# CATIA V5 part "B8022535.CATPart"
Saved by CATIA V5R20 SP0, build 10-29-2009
Part number: B8022535
Revision: 7
Definition: design
Nomenclature: B8022535
Source: made
Description: NOT SPECIFIED
Bounding box of the stored display mesh (mm): x -22.5 to 22.5, y -22.5 to 22.5, z -10 to 35
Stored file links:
  C:\Users\Utente\Desktop\3D files B802\B8022535.CATPart
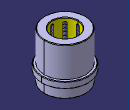
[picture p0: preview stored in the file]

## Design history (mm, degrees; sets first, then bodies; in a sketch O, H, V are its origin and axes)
Body1 "MANIFOLD_SOLID_BREP #38" (main body)
  Solid1: solid without history
Body2 "MANIFOLD_SOLID_BREP #76"
  Solid2: solid without history
Body3 "MANIFOLD_SOLID_BREP #114"
  Solid3: solid without history
Body4 "MANIFOLD_SOLID_BREP #152"
  Solid4: solid without history
Body5 "MANIFOLD_SOLID_BREP #190"
  Solid5: solid without history
Body6 "MANIFOLD_SOLID_BREP #228"
  Solid6: solid without history
Body7 "MANIFOLD_SOLID_BREP #266"
  Solid7: solid without history
Body8 "MANIFOLD_SOLID_BREP #304"
  Solid8: solid without history
Body9 "MANIFOLD_SOLID_BREP #2364"
  Solid9: solid without history
Body10 "MANIFOLD_SOLID_BREP #2402"
  Solid10: solid without history
Body11 "MANIFOLD_SOLID_BREP #2440"
  Solid11: solid without history
Body12 "MANIFOLD_SOLID_BREP #2478"
  Solid12: solid without history
Body13 "MANIFOLD_SOLID_BREP #2516"
  Solid13: solid without history
Body14 "MANIFOLD_SOLID_BREP #2554"
  Solid14: solid without history
Body15 "MANIFOLD_SOLID_BREP #2592"
  Solid15: solid without history
Body16 "MANIFOLD_SOLID_BREP #2630"
  Solid16: solid without history
Body17 "MANIFOLD_SOLID_BREP #2668"
  Solid17: solid without history
Body18 "MANIFOLD_SOLID_BREP #2706"
  Solid18: solid without history
Body19 "MANIFOLD_SOLID_BREP #2744"
  Solid19: solid without history
Body20 "MANIFOLD_SOLID_BREP #2782"
  Solid20: solid without history
Body21 "MANIFOLD_SOLID_BREP #2820"
  Solid21: solid without history
Body22 "MANIFOLD_SOLID_BREP #2858"
  Solid22: solid without history
Body23 "MANIFOLD_SOLID_BREP #2896"
  Solid23: solid without history
Body24 "MANIFOLD_SOLID_BREP #2934"
  Solid24: solid without history
Body25 "MANIFOLD_SOLID_BREP #2972"
  Solid25: solid without history
Body26 "MANIFOLD_SOLID_BREP #3010"
  Solid26: solid without history
Body27 "MANIFOLD_SOLID_BREP #3048"
  Solid27: solid without history
Body28 "MANIFOLD_SOLID_BREP #3086"
  Solid28: solid without history
Body29 "MANIFOLD_SOLID_BREP #3124"
  Solid29: solid without history
Body30 "MANIFOLD_SOLID_BREP #3162"
  Solid30: solid without history
Body31 "MANIFOLD_SOLID_BREP #3200"
  Solid31: solid without history
Body32 "MANIFOLD_SOLID_BREP #3238"
  Solid32: solid without history
Body33 "MANIFOLD_SOLID_BREP #3276"
  Solid33: solid without history
Body34 "MANIFOLD_SOLID_BREP #3314"
  Solid34: solid without history
Body35 "MANIFOLD_SOLID_BREP #3352"
  Solid35: solid without history
Body36 "MANIFOLD_SOLID_BREP #3390"
  Solid36: solid without history
Body37 "MANIFOLD_SOLID_BREP #3428"
  Solid37: solid without history
Body38 "MANIFOLD_SOLID_BREP #3466"
  Solid38: solid without history
Body39 "MANIFOLD_SOLID_BREP #3504"
  Solid39: solid without history
Body40 "MANIFOLD_SOLID_BREP #3542"
  Solid40: solid without history
Body41 "MANIFOLD_SOLID_BREP #3580"
  Solid41: solid without history
Body42 "MANIFOLD_SOLID_BREP #3618"
  Solid42: solid without history
Body43 "MANIFOLD_SOLID_BREP #3656"
  Solid43: solid without history
Body44 "MANIFOLD_SOLID_BREP #3694"
  Solid44: solid without history
Body45 "MANIFOLD_SOLID_BREP #3732"
  Solid45: solid without history
Body46 "MANIFOLD_SOLID_BREP #3770"
  Solid46: solid without history
Body47 "MANIFOLD_SOLID_BREP #3808"
  Solid47: solid without history
Body48 "MANIFOLD_SOLID_BREP #3846"
  Solid48: solid without history
Body49 "MANIFOLD_SOLID_BREP #3884"
  Solid49: solid without history
Body50 "MANIFOLD_SOLID_BREP #3922"
  Solid50: solid without history
Body51 "MANIFOLD_SOLID_BREP #3960"
  Solid51: solid without history
Body52 "MANIFOLD_SOLID_BREP #3998"
  Solid52: solid without history
Body53 "MANIFOLD_SOLID_BREP #4036"
  Solid53: solid without history
Body54 "MANIFOLD_SOLID_BREP #4074"
  Solid54: solid without history
Body55 "MANIFOLD_SOLID_BREP #4112"
  Solid55: solid without history
Body56 "MANIFOLD_SOLID_BREP #4150"
  Solid56: solid without history
Body57 "MANIFOLD_SOLID_BREP #4188"
  Solid57: solid without history
Body58 "MANIFOLD_SOLID_BREP #4226"
  Solid58: solid without history
Body59 "MANIFOLD_SOLID_BREP #4264"
  Solid59: solid without history
Body60 "MANIFOLD_SOLID_BREP #4302"
  Solid60: solid without history
Body61 "MANIFOLD_SOLID_BREP #4340"
  Solid61: solid without history
Body62 "MANIFOLD_SOLID_BREP #4378"
  Solid62: solid without history
Body63 "MANIFOLD_SOLID_BREP #4416"
  Solid63: solid without history
Body64 "MANIFOLD_SOLID_BREP #4454"
  Solid64: solid without history
Body65 "MANIFOLD_SOLID_BREP #4492"
  Solid65: solid without history
Body66 "MANIFOLD_SOLID_BREP #4530"
  Solid66: solid without history
Body67 "MANIFOLD_SOLID_BREP #4568"
  Solid67: solid without history
Body68 "MANIFOLD_SOLID_BREP #4606"
  Solid68: solid without history
Body69 "MANIFOLD_SOLID_BREP #4644"
  Solid69: solid without history
Body70 "MANIFOLD_SOLID_BREP #4682"
  Solid70: solid without history
Body71 "MANIFOLD_SOLID_BREP #4720"
  Solid71: solid without history
Body72 "MANIFOLD_SOLID_BREP #4758"
  Solid72: solid without history
Body73 "MANIFOLD_SOLID_BREP #4796"
  Solid73: solid without history
Body74 "MANIFOLD_SOLID_BREP #4834"
  Solid74: solid without history
Body75 "MANIFOLD_SOLID_BREP #4872"
  Solid75: solid without history
Body76 "MANIFOLD_SOLID_BREP #4910"
  Solid76: solid without history
Body77 "MANIFOLD_SOLID_BREP #4948"
  Solid77: solid without history
Body78 "MANIFOLD_SOLID_BREP #4986"
  Solid78: solid without history
Body79 "MANIFOLD_SOLID_BREP #5024"
  Solid79: solid without history
Body80 "MANIFOLD_SOLID_BREP #5062"
  Solid80: solid without history
Body81 "MANIFOLD_SOLID_BREP #5100"
  Solid81: solid without history
Body82 "MANIFOLD_SOLID_BREP #5138"
  Solid82: solid without history
Body83 "MANIFOLD_SOLID_BREP #5176"
  Solid83: solid without history
Body84 "MANIFOLD_SOLID_BREP #5214"
  Solid84: solid without history
Body85 "MANIFOLD_SOLID_BREP #5252"
  Solid85: solid without history
Body86 "MANIFOLD_SOLID_BREP #5290"
  Solid86: solid without history
Body87 "MANIFOLD_SOLID_BREP #5328"
  Solid87: solid without history
Body88 "MANIFOLD_SOLID_BREP #5366"
  Solid88: solid without history
Body89 "MANIFOLD_SOLID_BREP #5404"
  Solid89: solid without history
Body90 "MANIFOLD_SOLID_BREP #5442"
  Solid90: solid without history
Body91 "MANIFOLD_SOLID_BREP #5480"
  Solid91: solid without history
Body92 "MANIFOLD_SOLID_BREP #5518"
  Solid92: solid without history
Body93 "MANIFOLD_SOLID_BREP #5556"
  Solid93: solid without history
Body94 "MANIFOLD_SOLID_BREP #5594"
  Solid94: solid without history
Body95 "MANIFOLD_SOLID_BREP #5632"
  Solid95: solid without history
Body96 "MANIFOLD_SOLID_BREP #5670"
  Solid96: solid without history
Body97 "MANIFOLD_SOLID_BREP #5708"
  Solid97: solid without history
